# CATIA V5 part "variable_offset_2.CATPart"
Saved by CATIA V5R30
Part number: Part1
Bounding box of the stored display mesh (mm): x -92.294 to 37.025, y -35 to 35, z -60.324 to 55.06
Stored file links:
  D:\PROJECTS\CATIA V56R 2020\Resources\Parts File\c17_catia_v6_6r2020_prt\variable_offset_2.CATPart
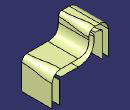
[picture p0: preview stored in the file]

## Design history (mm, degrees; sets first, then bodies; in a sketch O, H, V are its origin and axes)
Set1
  Sketch1 on zx-plane, origin (0, 0, 0), H (-1, 0, 0), V (0, 0, 1)
    point P1 (47.2937, 55.0598)
    line L1 (47.2937, 55.0598) -> (92.2937, 55.0598)
    line L2 (92.2937, 55.0598) -> (92.2937, -19.9402)
    length L2 = 75
    length L1 = 45
    horizontal: L1 H
    vertical: L2 V
  Extrude1: Element1 Sketch1, Lim1 35, Lim2 35
  Sketch2 on zx-plane, origin (0, 0, 0), H (-1, 0, 0), V (0, 0, 1)
    point P1 (47.2937, 55.0598)
    line L1 (47.2937, 55.0598) -> (47.2937, 35.0598)
    reference projected point E1 (47.2937, 55.0598) from Sketch1.P1
    length L1 = 20
    vertical: L1 V
    coincidence: P1 E1
  Extrude2: Element1 Sketch2, Lim1 35, Lim2 35
  Sketch3 on zx-plane, origin (0, 0, 0), H (-1, 0, 0), V (0, 0, 1)
    line L1 (22.975, 9.6765) -> (-37.025, 9.6765)
    line L2 (-37.025, 9.6765) -> (-37.025, -60.3235)
    length L1 = 60
    length L2 = 70
    horizontal: L1 H
    vertical: L2 V
  Extrude3: Element1 Sketch3, Lim1 35, Lim2 35
  Blend1: StartLimit {blendlimit Curve edge of Extrude2, Support Extrude2}, EndLimit {blendlimit Curve edge of Extrude3, Support Extrude3}
  Fillet1: radius 20, on edge [face of Extrude1 from Sketch1.L2 | face of Extrude1 from Sketch1.L1]
  Join1: Elements (Extrude2; Fillet1)
  Fillet2: radius 8, on edge [face of Extrude1 from Sketch1.L1 | face of Extrude2 from Sketch2.L1]
  Fillet3: radius 15, on edge [face of Extrude3 from Sketch3.L1 | face of Extrude3 from Sketch3.L2]
  Join2: Elements (Fillet3; Blend1; Fillet2)
  GSOVariableOffset1: GlobalSurface Join2, TrickyFaces (face of Fillet2; face of Fillet3), ListOfConstraints Blend1
Body1 (main body)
